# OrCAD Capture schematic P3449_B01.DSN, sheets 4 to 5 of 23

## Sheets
4 0019_40Pin GPIO expansion heade: size Custom
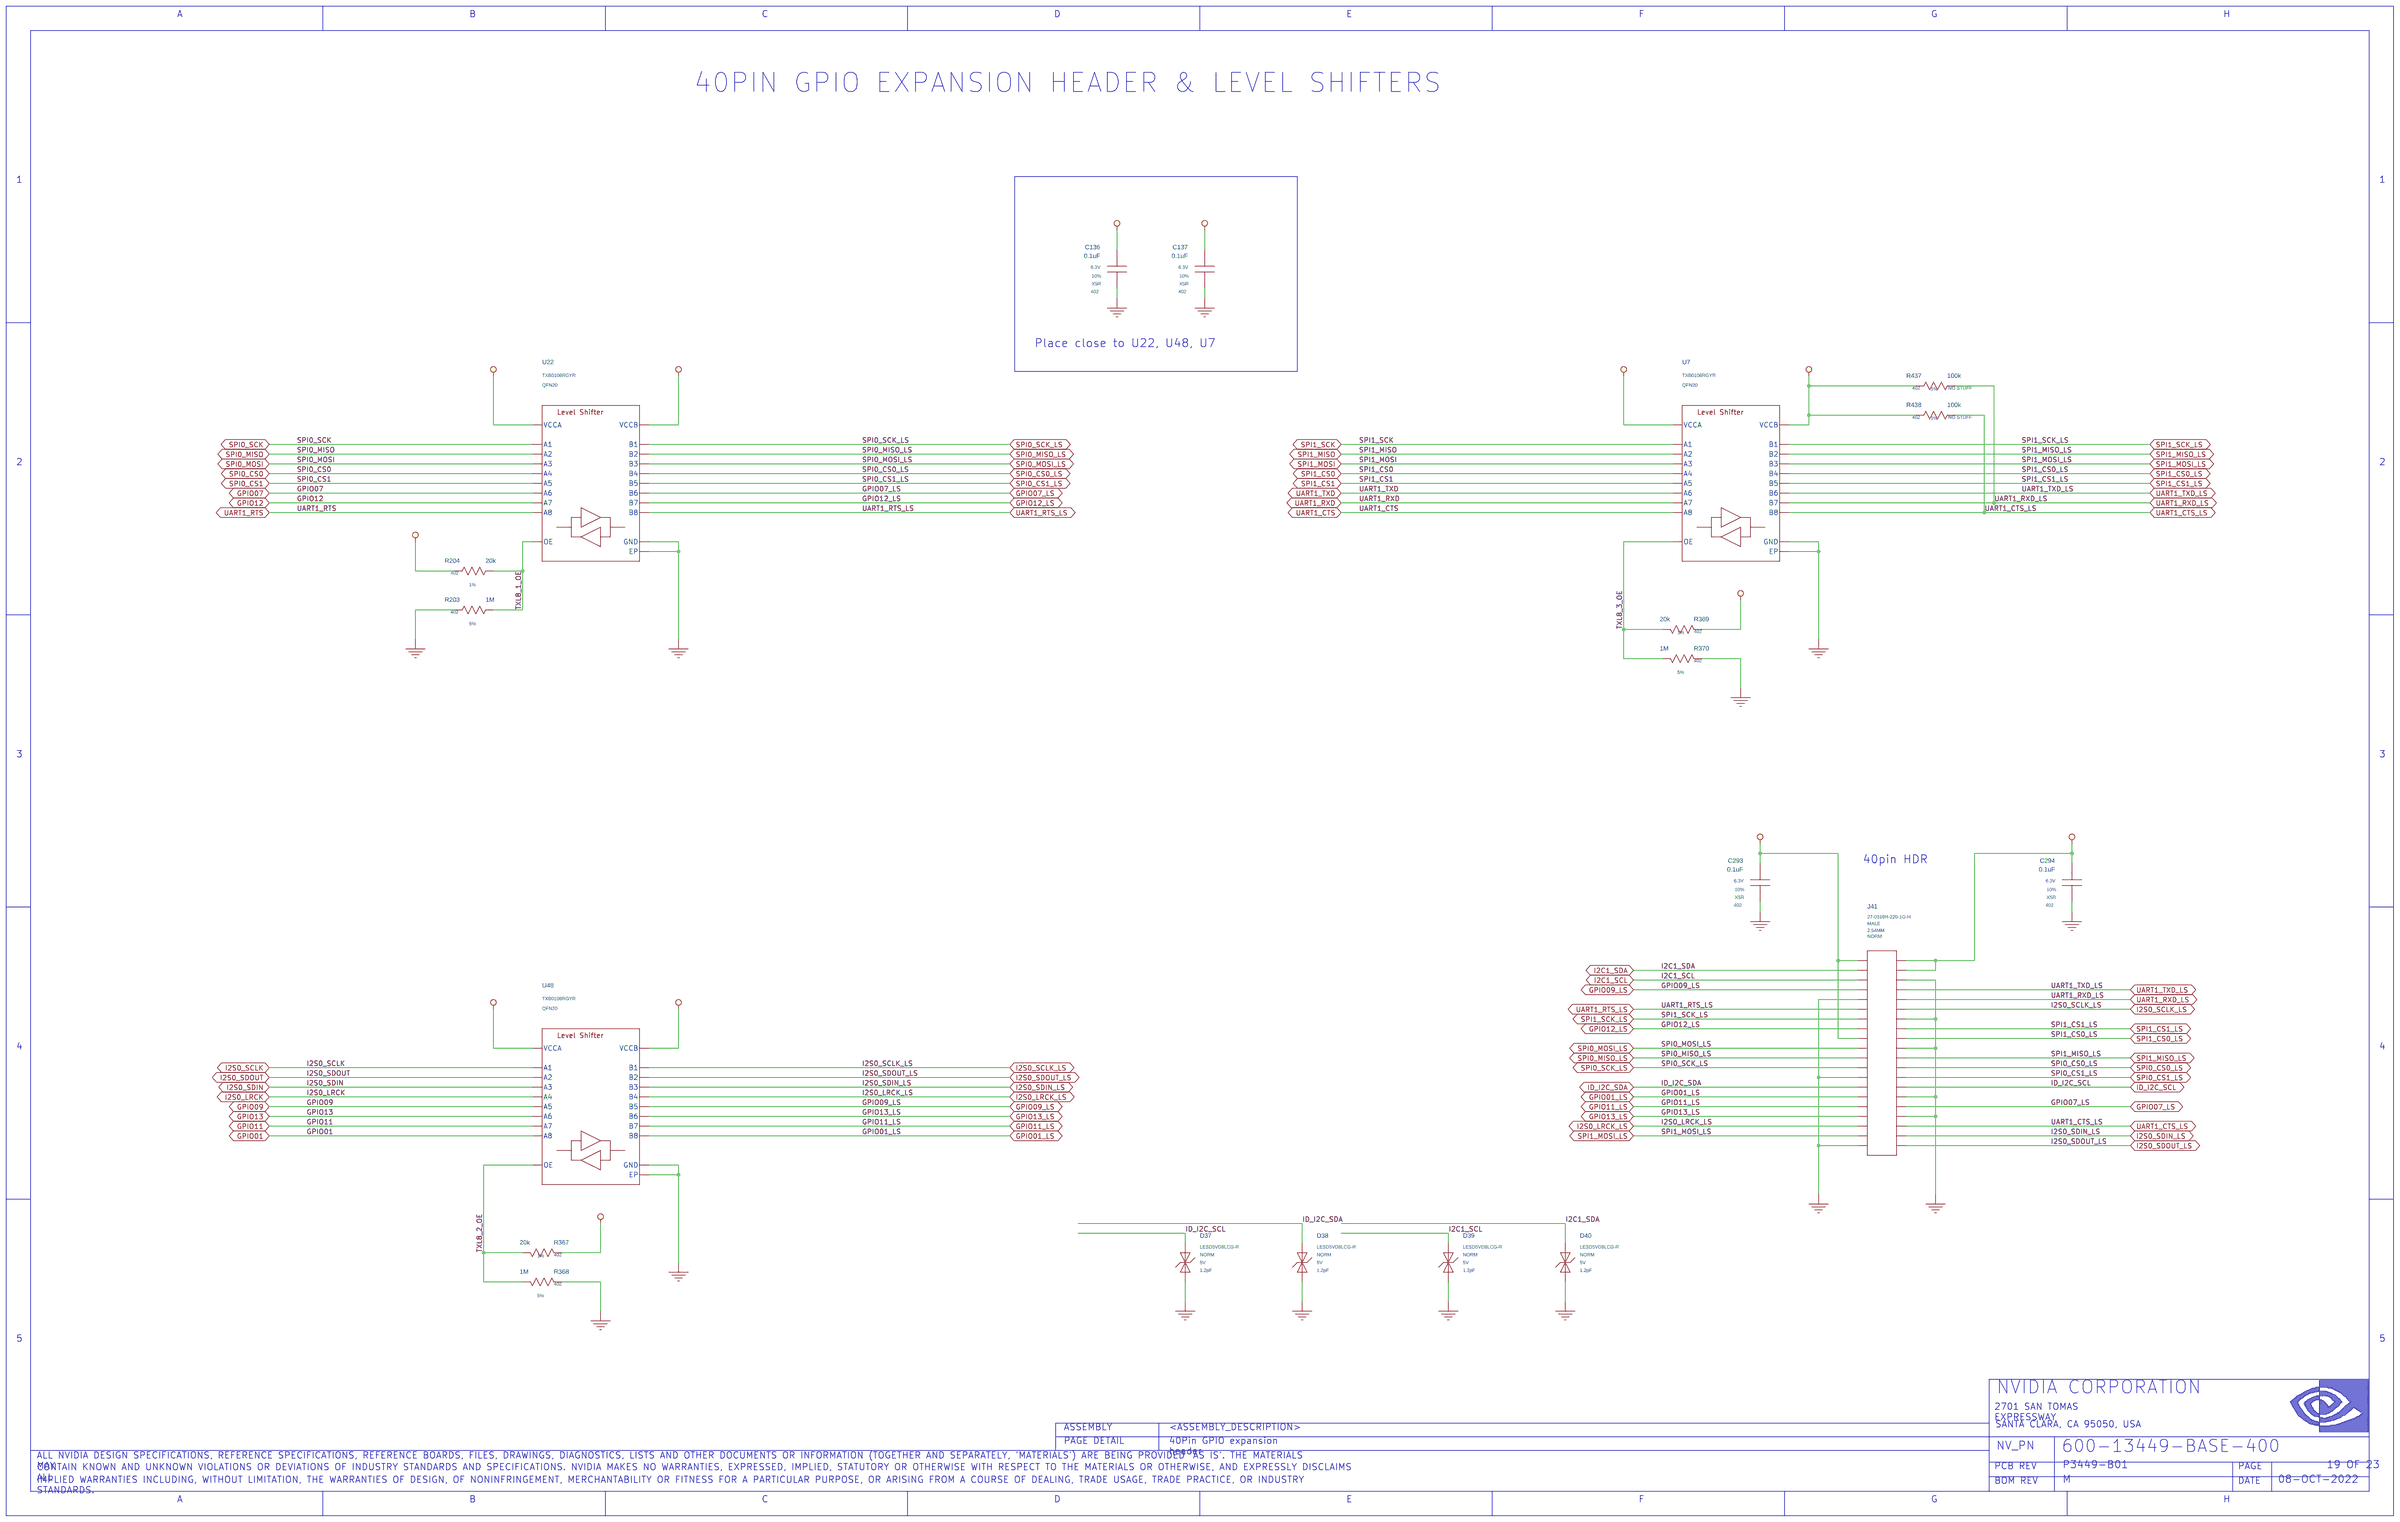
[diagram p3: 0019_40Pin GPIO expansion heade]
5 0018_CAM Connector: size Custom
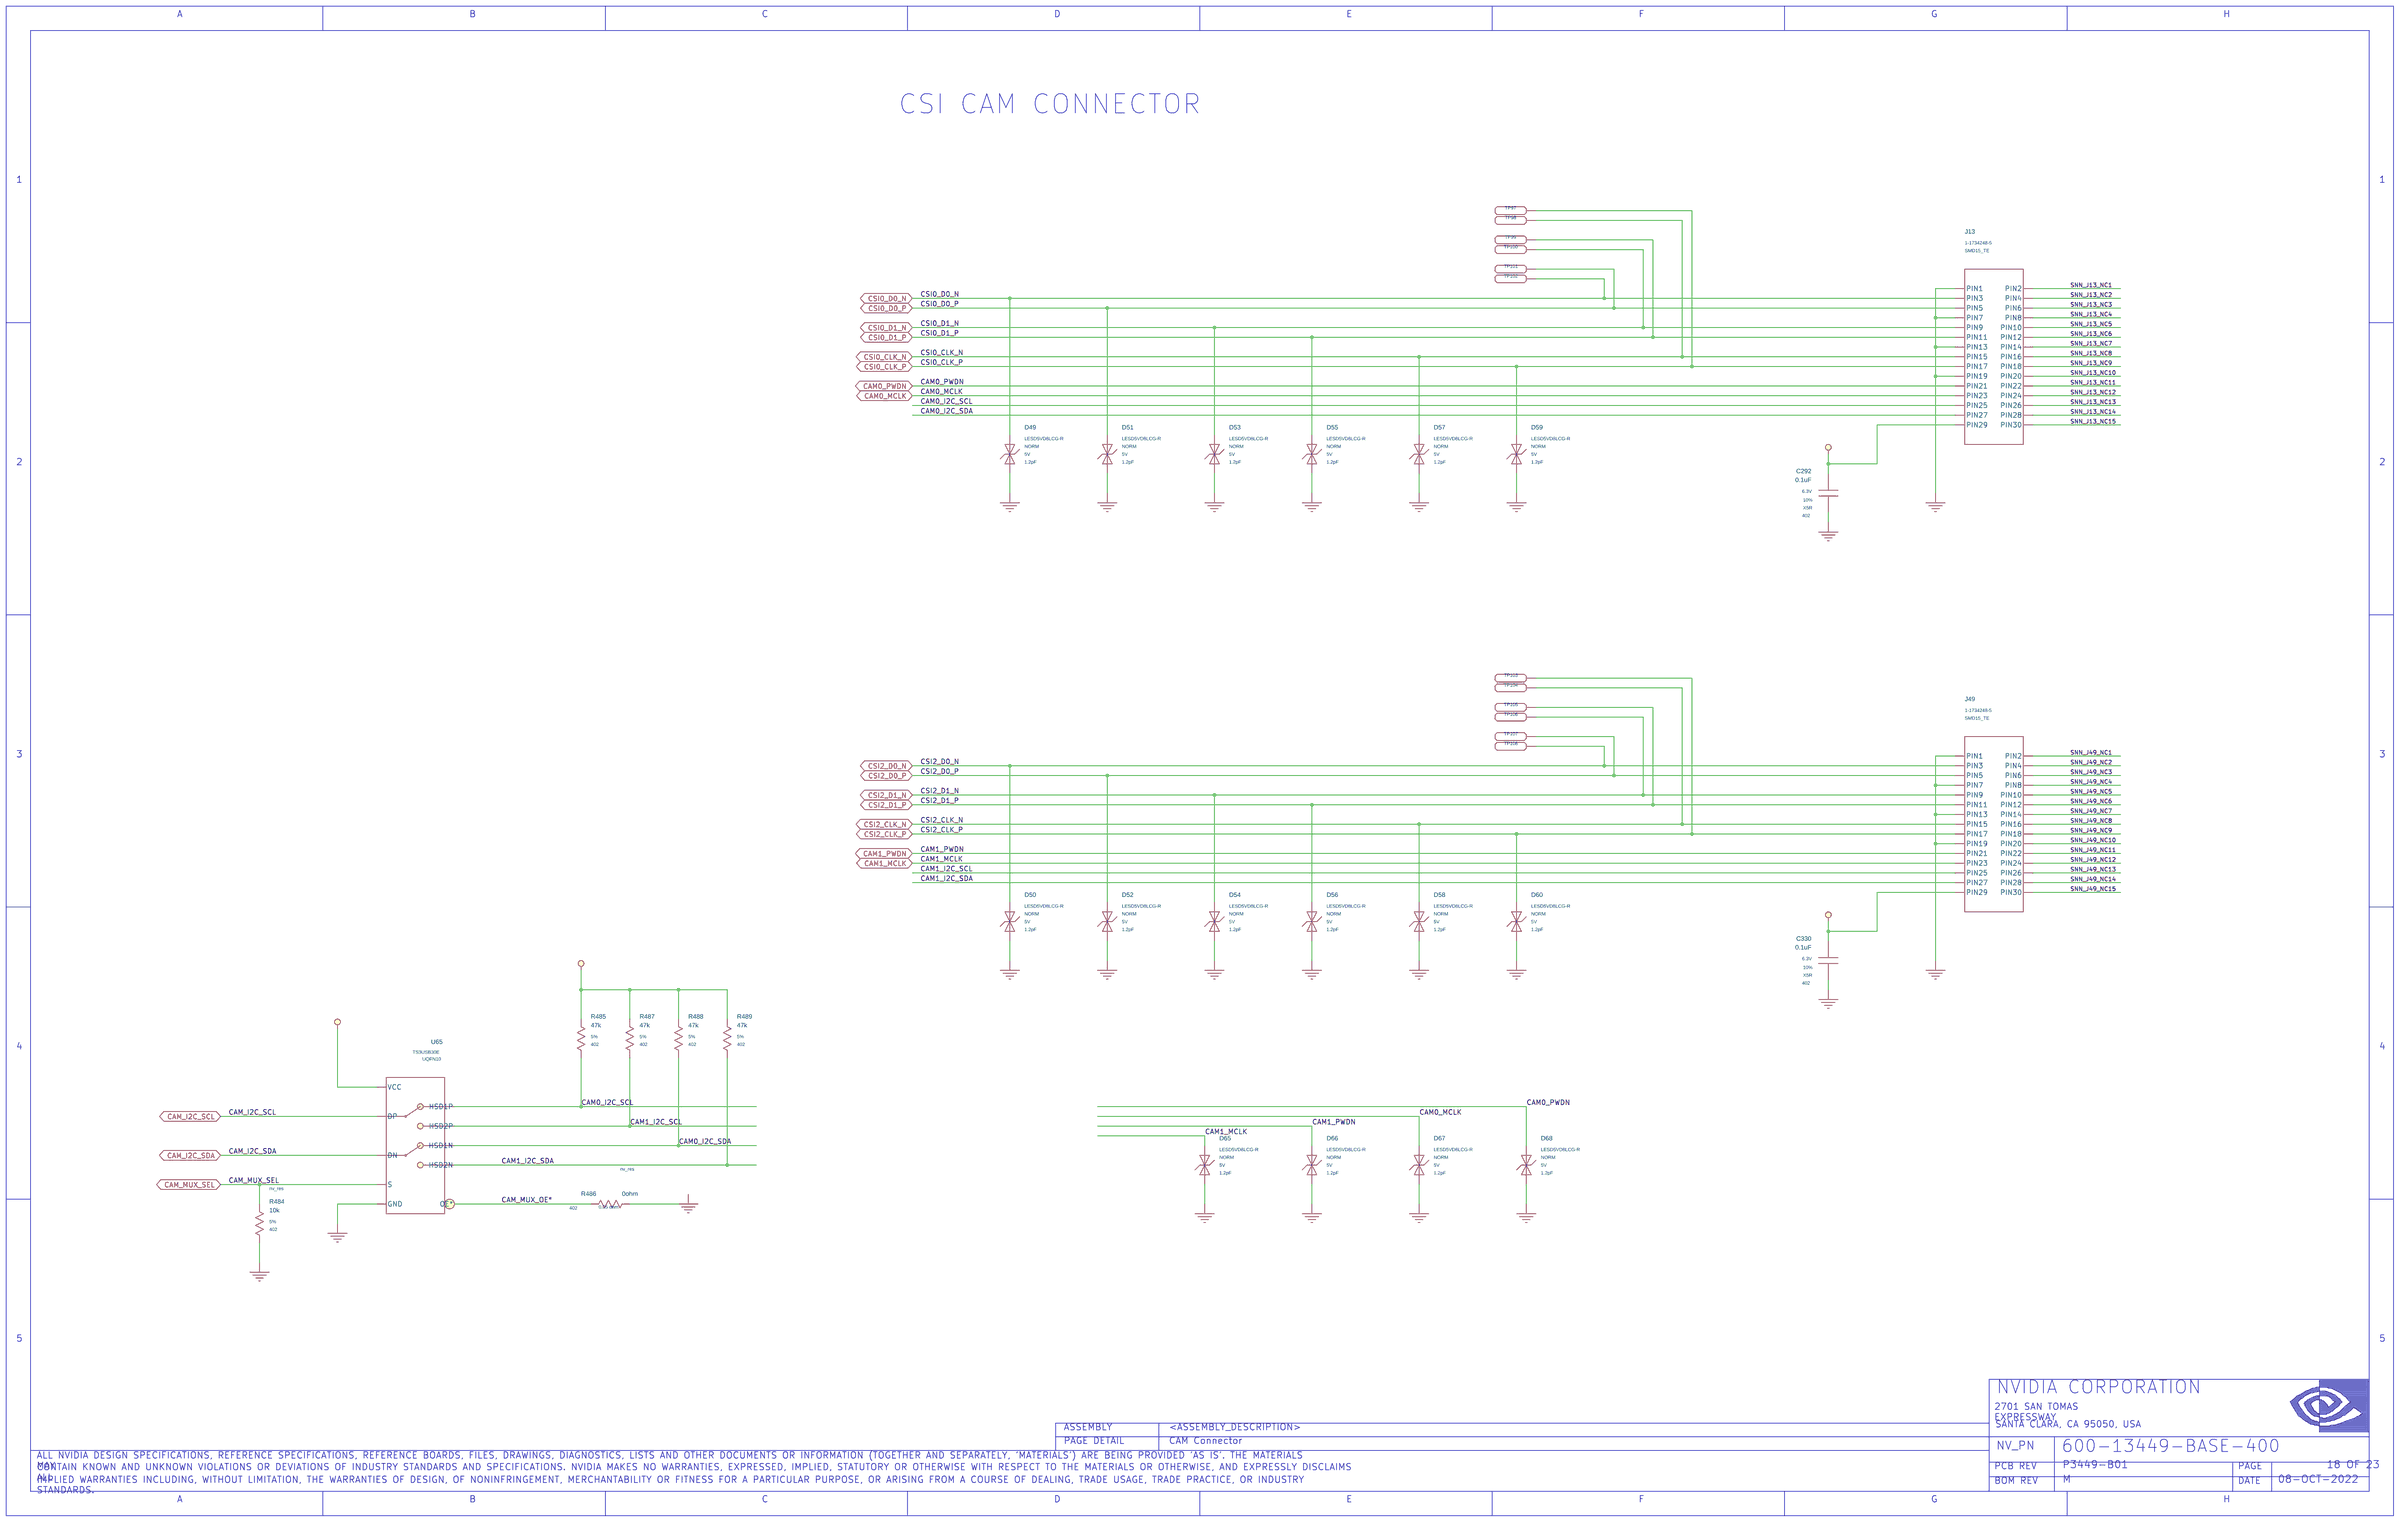
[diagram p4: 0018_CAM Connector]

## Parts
sheet 0018_CAM Connector
C292  0.1uF  [402]
C330  0.1uF  [402]
D49  D_ESD  [DIODE_SMD_010X060]
D50  D_ESD  [DIODE_SMD_010X060]
D51  D_ESD  [DIODE_SMD_010X060]
D52  D_ESD  [DIODE_SMD_010X060]
D53  D_ESD  [DIODE_SMD_010X060]
D54  D_ESD  [DIODE_SMD_010X060]
D55  D_ESD  [DIODE_SMD_010X060]
D56  D_ESD  [DIODE_SMD_010X060]
D57  D_ESD  [DIODE_SMD_010X060]
D58  D_ESD  [DIODE_SMD_010X060]
D59  D_ESD  [DIODE_SMD_010X060]
D60  D_ESD  [DIODE_SMD_010X060]
D65  D_ESD  [DIODE_SMD_010X060]
D66  D_ESD  [DIODE_SMD_010X060]
D67  D_ESD  [DIODE_SMD_010X060]
D68  D_ESD  [DIODE_SMD_010X060]
J13  CON_FPC_15  [CON_FFC_030_SMD_ST_F_P010_ZIF]
J49  CON_FPC_15  [CON_FFC_030_SMD_ST_F_P010_ZIF]
R484  10k  [402]
R485  47k  [402]
R486  0ohm  [402]
R487  47k  [402]
R488  47k  [402]
R489  47k  [402]
TP97  LABTESTPOINT  [LTPB071C125D045C025P]
TP98  LABTESTPOINT  [LTPB071C125D045C025P]
TP99  LABTESTPOINT  [LTPB071C125D045C025P]
TP100  LABTESTPOINT  [LTPB071C125D045C025P]
TP101  LABTESTPOINT  [LTPB071C125D045C025P]
TP102  LABTESTPOINT  [LTPB071C125D045C025P]
TP103  LABTESTPOINT  [LTPB071C125D045C025P]
TP104  LABTESTPOINT  [LTPB071C125D045C025P]
TP105  LABTESTPOINT  [LTPB071C125D045C025P]
TP106  LABTESTPOINT  [LTPB071C125D045C025P]
TP107  LABTESTPOINT  [LTPB071C125D045C025P]
TP108  LABTESTPOINT  [LTPB071C125D045C025P]
U65  U_SW_ANA_USB  [QFN010R_P040_0018X0014]
sheet 0019_40Pin GPIO expansion heade
C136  0.1uF  [402]
C137  0.1uF  [402]
C293  0.1uF  [402]
C294  0.1uF  [402]
D37  D_ESD  [DIODE_SMD_010X060]
D38  D_ESD  [DIODE_SMD_010X060]
D39  D_ESD  [DIODE_SMD_010X060]
D40  D_ESD  [DIODE_SMD_010X060]
J41  HDR_2X20  [CON_HDR_002X020_TH_ST_M_P025_B]
R203  1M  [402]
R204  20k  [402]
R367  20k  [402]
R368  1M  [402]
R369  20k  [402]
R370  1M  [402]
R437  100k  [402]
R438  100k  [402]
U7  U_LEVSHFT_TXB0108  [QFN020R_P050_0045X0035_T031X021_VIAS]
U22  U_LEVSHFT_TXB0108  [QFN020R_P050_0045X0035_T031X021_VIAS]
U48  U_LEVSHFT_TXB0108  [QFN020R_P050_0045X0035_T031X021_VIAS]

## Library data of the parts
C292 = C#1: ASSEMBLY: CAM; CDS_LIB: discrete; CDS_PART_NAME: C_0402-0.1UF,X5R,10%,6.3V,039-0007-000; CDS_PHYS_PART_NAME: C_0402-0.1UF,X5R,10%,6.3V,039-0007-000-0.1UF,039-0007-000; CDS_SEC: 1; CHIPS_PART_NAME: C; DEVICE_TYPENAME: C_0402-01UFX5R1063V039-0007-000-01UF039-0007-000; DRAWING: @P3449_B01_LIB.P3449_B01(SCH_1):PAGE18; ESL: N/A; ESR: N/A; MAT: X5R; MAX_VOLTAGE: 6.3V; NV_PN: 039-0007-000; PATH: I15; PHYS_PAGE: 18; ROT: 2; SEC: 1; SIGNAL_MODEL: nv_cap; TOL: 10%; VER: 1; XY: (-2800,5100)
C330 = C#1: ASSEMBLY: CAM; CDS_LIB: discrete; CDS_PART_NAME: C_0402-0.1UF,X5R,10%,6.3V,039-0007-000; CDS_PHYS_PART_NAME: C_0402-0.1UF,X5R,10%,6.3V,039-0007-000-0.1UF,039-0007-000; CDS_SEC: 1; CHIPS_PART_NAME: C; DEVICE_TYPENAME: C_0402-01UFX5R1063V039-0007-000-01UF039-0007-000; DRAWING: @P3449_B01_LIB.P3449_B01(SCH_1):PAGE18; ESL: N/A; ESR: N/A; MAT: X5R; MAX_VOLTAGE: 6.3V; NV_PN: 039-0007-000; PATH: I27; PHYS_PAGE: 18; ROT: 2; SEC: 1; SIGNAL_MODEL: nv_cap; TOL: 10%; VER: 1; XY: (-2800,2700)
D49 = D_ESD: ASSEMBLY: CAM; BREAKDOWN_VOLTAGE_MIN_TYP: 5.5V; CAPACITANCE_MAX_TYP: 1.2pF; CDS_LIB: discrete; CDS_PART_NAME: D_ESD_NORM-LESD5VD8LCG-R,1 LINE,BI-DIRECTIONAL,5V,0.05UA,5.5V,10V@2A,1.2PF,090-0172-000; CDS_PHYS_PART_NAME: D_ESD_NORM-LESD5VD8LCG-R,1 LINE,BI-DIRECTIONAL,5V,0.05UA,5.5V,10V@2A,1.2PF,090-0172-000-090-0172-000; CDS_SEC: 1; CLAMPING_VOLTAGE: 10V@2A; CONFIGURATION: 1 Line; DEVICE_TYPENAME: D_ESD_NORM-LESD5VD8LCG-R1LINEBI-DIRECTIONAL5V005UA55V10V2A12PF090-0172-000-090-0172-000; DRAWING: @P3449_B01_LIB.P3449_B01(SCH_1):PAGE18; MAX_REVERSE_LEAKAGE_CURRENT: 0.05uA; MAX_REVERSE_VOLTAGE: 5V; NV_NAME: LESD5VD8LCG-R; NV_PN: 090-0172-000; PACK_TYPE: NORM; PATH: I32; PHYS_PAGE: 18; POLARITY: Bi-Directional; ROT: 0; SEC: 1; VER: 2; XY: (-7000,5300)
D50 = D_ESD: ASSEMBLY: CAM; BREAKDOWN_VOLTAGE_MIN_TYP: 5.5V; CAPACITANCE_MAX_TYP: 1.2pF; CDS_LIB: discrete; CDS_PART_NAME: D_ESD_NORM-LESD5VD8LCG-R,1 LINE,BI-DIRECTIONAL,5V,0.05UA,5.5V,10V@2A,1.2PF,090-0172-000; CDS_PHYS_PART_NAME: D_ESD_NORM-LESD5VD8LCG-R,1 LINE,BI-DIRECTIONAL,5V,0.05UA,5.5V,10V@2A,1.2PF,090-0172-000-090-0172-000; CDS_SEC: 1; CLAMPING_VOLTAGE: 10V@2A; CONFIGURATION: 1 Line; DEVICE_TYPENAME: D_ESD_NORM-LESD5VD8LCG-R1LINEBI-DIRECTIONAL5V005UA55V10V2A12PF090-0172-000-090-0172-000; DRAWING: @P3449_B01_LIB.P3449_B01(SCH_1):PAGE18; MAX_REVERSE_LEAKAGE_CURRENT: 0.05uA; MAX_REVERSE_VOLTAGE: 5V; NV_NAME: LESD5VD8LCG-R; NV_PN: 090-0172-000; PACK_TYPE: NORM; PATH: I54; PHYS_PAGE: 18; POLARITY: Bi-Directional; ROT: 0; SEC: 1; VER: 2; XY: (-7000,2900)
D51 = D_ESD: ASSEMBLY: CAM; BREAKDOWN_VOLTAGE_MIN_TYP: 5.5V; CAPACITANCE_MAX_TYP: 1.2pF; CDS_LIB: discrete; CDS_PART_NAME: D_ESD_NORM-LESD5VD8LCG-R,1 LINE,BI-DIRECTIONAL,5V,0.05UA,5.5V,10V@2A,1.2PF,090-0172-000; CDS_PHYS_PART_NAME: D_ESD_NORM-LESD5VD8LCG-R,1 LINE,BI-DIRECTIONAL,5V,0.05UA,5.5V,10V@2A,1.2PF,090-0172-000-090-0172-000; CDS_SEC: 1; CLAMPING_VOLTAGE: 10V@2A; CONFIGURATION: 1 Line; DEVICE_TYPENAME: D_ESD_NORM-LESD5VD8LCG-R1LINEBI-DIRECTIONAL5V005UA55V10V2A12PF090-0172-000-090-0172-000; DRAWING: @P3449_B01_LIB.P3449_B01(SCH_1):PAGE18; MAX_REVERSE_LEAKAGE_CURRENT: 0.05uA; MAX_REVERSE_VOLTAGE: 5V; NV_NAME: LESD5VD8LCG-R; NV_PN: 090-0172-000; PACK_TYPE: NORM; PATH: I33; PHYS_PAGE: 18; POLARITY: Bi-Directional; ROT: 0; SEC: 1; VER: 2; XY: (-6500,5300)
D52 = D_ESD: ASSEMBLY: CAM; BREAKDOWN_VOLTAGE_MIN_TYP: 5.5V; CAPACITANCE_MAX_TYP: 1.2pF; CDS_LIB: discrete; CDS_PART_NAME: D_ESD_NORM-LESD5VD8LCG-R,1 LINE,BI-DIRECTIONAL,5V,0.05UA,5.5V,10V@2A,1.2PF,090-0172-000; CDS_PHYS_PART_NAME: D_ESD_NORM-LESD5VD8LCG-R,1 LINE,BI-DIRECTIONAL,5V,0.05UA,5.5V,10V@2A,1.2PF,090-0172-000-090-0172-000; CDS_SEC: 1; CLAMPING_VOLTAGE: 10V@2A; CONFIGURATION: 1 Line; DEVICE_TYPENAME: D_ESD_NORM-LESD5VD8LCG-R1LINEBI-DIRECTIONAL5V005UA55V10V2A12PF090-0172-000-090-0172-000; DRAWING: @P3449_B01_LIB.P3449_B01(SCH_1):PAGE18; MAX_REVERSE_LEAKAGE_CURRENT: 0.05uA; MAX_REVERSE_VOLTAGE: 5V; NV_NAME: LESD5VD8LCG-R; NV_PN: 090-0172-000; PACK_TYPE: NORM; PATH: I52; PHYS_PAGE: 18; POLARITY: Bi-Directional; ROT: 0; SEC: 1; VER: 2; XY: (-6500,2900)
D53 = D_ESD: ASSEMBLY: CAM; BREAKDOWN_VOLTAGE_MIN_TYP: 5.5V; CAPACITANCE_MAX_TYP: 1.2pF; CDS_LIB: discrete; CDS_PART_NAME: D_ESD_NORM-LESD5VD8LCG-R,1 LINE,BI-DIRECTIONAL,5V,0.05UA,5.5V,10V@2A,1.2PF,090-0172-000; CDS_PHYS_PART_NAME: D_ESD_NORM-LESD5VD8LCG-R,1 LINE,BI-DIRECTIONAL,5V,0.05UA,5.5V,10V@2A,1.2PF,090-0172-000-090-0172-000; CDS_SEC: 1; CLAMPING_VOLTAGE: 10V@2A; CONFIGURATION: 1 Line; DEVICE_TYPENAME: D_ESD_NORM-LESD5VD8LCG-R1LINEBI-DIRECTIONAL5V005UA55V10V2A12PF090-0172-000-090-0172-000; DRAWING: @P3449_B01_LIB.P3449_B01(SCH_1):PAGE18; MAX_REVERSE_LEAKAGE_CURRENT: 0.05uA; MAX_REVERSE_VOLTAGE: 5V; NV_NAME: LESD5VD8LCG-R; NV_PN: 090-0172-000; PACK_TYPE: NORM; PATH: I35; PHYS_PAGE: 18; POLARITY: Bi-Directional; ROT: 0; SEC: 1; VER: 2; XY: (-5950,5300)
D54 = D_ESD: ASSEMBLY: CAM; BREAKDOWN_VOLTAGE_MIN_TYP: 5.5V; CAPACITANCE_MAX_TYP: 1.2pF; CDS_LIB: discrete; CDS_PART_NAME: D_ESD_NORM-LESD5VD8LCG-R,1 LINE,BI-DIRECTIONAL,5V,0.05UA,5.5V,10V@2A,1.2PF,090-0172-000; CDS_PHYS_PART_NAME: D_ESD_NORM-LESD5VD8LCG-R,1 LINE,BI-DIRECTIONAL,5V,0.05UA,5.5V,10V@2A,1.2PF,090-0172-000-090-0172-000; CDS_SEC: 1; CLAMPING_VOLTAGE: 10V@2A; CONFIGURATION: 1 Line; DEVICE_TYPENAME: D_ESD_NORM-LESD5VD8LCG-R1LINEBI-DIRECTIONAL5V005UA55V10V2A12PF090-0172-000-090-0172-000; DRAWING: @P3449_B01_LIB.P3449_B01(SCH_1):PAGE18; MAX_REVERSE_LEAKAGE_CURRENT: 0.05uA; MAX_REVERSE_VOLTAGE: 5V; NV_NAME: LESD5VD8LCG-R; NV_PN: 090-0172-000; PACK_TYPE: NORM; PATH: I51; PHYS_PAGE: 18; POLARITY: Bi-Directional; ROT: 0; SEC: 1; VER: 2; XY: (-5950,2900)
D55 = D_ESD: ASSEMBLY: CAM; BREAKDOWN_VOLTAGE_MIN_TYP: 5.5V; CAPACITANCE_MAX_TYP: 1.2pF; CDS_LIB: discrete; CDS_PART_NAME: D_ESD_NORM-LESD5VD8LCG-R,1 LINE,BI-DIRECTIONAL,5V,0.05UA,5.5V,10V@2A,1.2PF,090-0172-000; CDS_PHYS_PART_NAME: D_ESD_NORM-LESD5VD8LCG-R,1 LINE,BI-DIRECTIONAL,5V,0.05UA,5.5V,10V@2A,1.2PF,090-0172-000-090-0172-000; CDS_SEC: 1; CLAMPING_VOLTAGE: 10V@2A; CONFIGURATION: 1 Line; DEVICE_TYPENAME: D_ESD_NORM-LESD5VD8LCG-R1LINEBI-DIRECTIONAL5V005UA55V10V2A12PF090-0172-000-090-0172-000; DRAWING: @P3449_B01_LIB.P3449_B01(SCH_1):PAGE18; MAX_REVERSE_LEAKAGE_CURRENT: 0.05uA; MAX_REVERSE_VOLTAGE: 5V; NV_NAME: LESD5VD8LCG-R; NV_PN: 090-0172-000; PACK_TYPE: NORM; PATH: I34; PHYS_PAGE: 18; POLARITY: Bi-Directional; ROT: 0; SEC: 1; VER: 2; XY: (-5450,5300)
D56 = D_ESD: ASSEMBLY: CAM; BREAKDOWN_VOLTAGE_MIN_TYP: 5.5V; CAPACITANCE_MAX_TYP: 1.2pF; CDS_LIB: discrete; CDS_PART_NAME: D_ESD_NORM-LESD5VD8LCG-R,1 LINE,BI-DIRECTIONAL,5V,0.05UA,5.5V,10V@2A,1.2PF,090-0172-000; CDS_PHYS_PART_NAME: D_ESD_NORM-LESD5VD8LCG-R,1 LINE,BI-DIRECTIONAL,5V,0.05UA,5.5V,10V@2A,1.2PF,090-0172-000-090-0172-000; CDS_SEC: 1; CLAMPING_VOLTAGE: 10V@2A; CONFIGURATION: 1 Line; DEVICE_TYPENAME: D_ESD_NORM-LESD5VD8LCG-R1LINEBI-DIRECTIONAL5V005UA55V10V2A12PF090-0172-000-090-0172-000; DRAWING: @P3449_B01_LIB.P3449_B01(SCH_1):PAGE18; MAX_REVERSE_LEAKAGE_CURRENT: 0.05uA; MAX_REVERSE_VOLTAGE: 5V; NV_NAME: LESD5VD8LCG-R; NV_PN: 090-0172-000; PACK_TYPE: NORM; PATH: I49; PHYS_PAGE: 18; POLARITY: Bi-Directional; ROT: 0; SEC: 1; VER: 2; XY: (-5450,2900)
D57 = D_ESD: ASSEMBLY: CAM; BREAKDOWN_VOLTAGE_MIN_TYP: 5.5V; CAPACITANCE_MAX_TYP: 1.2pF; CDS_LIB: discrete; CDS_PART_NAME: D_ESD_NORM-LESD5VD8LCG-R,1 LINE,BI-DIRECTIONAL,5V,0.05UA,5.5V,10V@2A,1.2PF,090-0172-000; CDS_PHYS_PART_NAME: D_ESD_NORM-LESD5VD8LCG-R,1 LINE,BI-DIRECTIONAL,5V,0.05UA,5.5V,10V@2A,1.2PF,090-0172-000-090-0172-000; CDS_SEC: 1; CLAMPING_VOLTAGE: 10V@2A; CONFIGURATION: 1 Line; DEVICE_TYPENAME: D_ESD_NORM-LESD5VD8LCG-R1LINEBI-DIRECTIONAL5V005UA55V10V2A12PF090-0172-000-090-0172-000; DRAWING: @P3449_B01_LIB.P3449_B01(SCH_1):PAGE18; MAX_REVERSE_LEAKAGE_CURRENT: 0.05uA; MAX_REVERSE_VOLTAGE: 5V; NV_NAME: LESD5VD8LCG-R; NV_PN: 090-0172-000; PACK_TYPE: NORM; PATH: I37; PHYS_PAGE: 18; POLARITY: Bi-Directional; ROT: 0; SEC: 1; VER: 2; XY: (-4900,5300)
D58 = D_ESD: ASSEMBLY: CAM; BREAKDOWN_VOLTAGE_MIN_TYP: 5.5V; CAPACITANCE_MAX_TYP: 1.2pF; CDS_LIB: discrete; CDS_PART_NAME: D_ESD_NORM-LESD5VD8LCG-R,1 LINE,BI-DIRECTIONAL,5V,0.05UA,5.5V,10V@2A,1.2PF,090-0172-000; CDS_PHYS_PART_NAME: D_ESD_NORM-LESD5VD8LCG-R,1 LINE,BI-DIRECTIONAL,5V,0.05UA,5.5V,10V@2A,1.2PF,090-0172-000-090-0172-000; CDS_SEC: 1; CLAMPING_VOLTAGE: 10V@2A; CONFIGURATION: 1 Line; DEVICE_TYPENAME: D_ESD_NORM-LESD5VD8LCG-R1LINEBI-DIRECTIONAL5V005UA55V10V2A12PF090-0172-000-090-0172-000; DRAWING: @P3449_B01_LIB.P3449_B01(SCH_1):PAGE18; MAX_REVERSE_LEAKAGE_CURRENT: 0.05uA; MAX_REVERSE_VOLTAGE: 5V; NV_NAME: LESD5VD8LCG-R; NV_PN: 090-0172-000; PACK_TYPE: NORM; PATH: I47; PHYS_PAGE: 18; POLARITY: Bi-Directional; ROT: 0; SEC: 1; VER: 2; XY: (-4900,2900)
D59 = D_ESD: ASSEMBLY: CAM; BREAKDOWN_VOLTAGE_MIN_TYP: 5.5V; CAPACITANCE_MAX_TYP: 1.2pF; CDS_LIB: discrete; CDS_PART_NAME: D_ESD_NORM-LESD5VD8LCG-R,1 LINE,BI-DIRECTIONAL,5V,0.05UA,5.5V,10V@2A,1.2PF,090-0172-000; CDS_PHYS_PART_NAME: D_ESD_NORM-LESD5VD8LCG-R,1 LINE,BI-DIRECTIONAL,5V,0.05UA,5.5V,10V@2A,1.2PF,090-0172-000-090-0172-000; CDS_SEC: 1; CLAMPING_VOLTAGE: 10V@2A; CONFIGURATION: 1 Line; DEVICE_TYPENAME: D_ESD_NORM-LESD5VD8LCG-R1LINEBI-DIRECTIONAL5V005UA55V10V2A12PF090-0172-000-090-0172-000; DRAWING: @P3449_B01_LIB.P3449_B01(SCH_1):PAGE18; MAX_REVERSE_LEAKAGE_CURRENT: 0.05uA; MAX_REVERSE_VOLTAGE: 5V; NV_NAME: LESD5VD8LCG-R; NV_PN: 090-0172-000; PACK_TYPE: NORM; PATH: I36; PHYS_PAGE: 18; POLARITY: Bi-Directional; ROT: 0; SEC: 1; VER: 2; XY: (-4400,5300)
D60 = D_ESD: ASSEMBLY: CAM; BREAKDOWN_VOLTAGE_MIN_TYP: 5.5V; CAPACITANCE_MAX_TYP: 1.2pF; CDS_LIB: discrete; CDS_PART_NAME: D_ESD_NORM-LESD5VD8LCG-R,1 LINE,BI-DIRECTIONAL,5V,0.05UA,5.5V,10V@2A,1.2PF,090-0172-000; CDS_PHYS_PART_NAME: D_ESD_NORM-LESD5VD8LCG-R,1 LINE,BI-DIRECTIONAL,5V,0.05UA,5.5V,10V@2A,1.2PF,090-0172-000-090-0172-000; CDS_SEC: 1; CLAMPING_VOLTAGE: 10V@2A; CONFIGURATION: 1 Line; DEVICE_TYPENAME: D_ESD_NORM-LESD5VD8LCG-R1LINEBI-DIRECTIONAL5V005UA55V10V2A12PF090-0172-000-090-0172-000; DRAWING: @P3449_B01_LIB.P3449_B01(SCH_1):PAGE18; MAX_REVERSE_LEAKAGE_CURRENT: 0.05uA; MAX_REVERSE_VOLTAGE: 5V; NV_NAME: LESD5VD8LCG-R; NV_PN: 090-0172-000; PACK_TYPE: NORM; PATH: I45; PHYS_PAGE: 18; POLARITY: Bi-Directional; ROT: 0; SEC: 1; VER: 2; XY: (-4400,2900)
D65 = D_ESD: ASSEMBLY: CAM; BREAKDOWN_VOLTAGE_MIN_TYP: 5.5V; CAPACITANCE_MAX_TYP: 1.2pF; CDS_LIB: discrete; CDS_PART_NAME: D_ESD_NORM-LESD5VD8LCG-R,1 LINE,BI-DIRECTIONAL,5V,0.05UA,5.5V,10V@2A,1.2PF,090-0172-000; CDS_PHYS_PART_NAME: D_ESD_NORM-LESD5VD8LCG-R,1 LINE,BI-DIRECTIONAL,5V,0.05UA,5.5V,10V@2A,1.2PF,090-0172-000-090-0172-000; CDS_SEC: 1; CLAMPING_VOLTAGE: 10V@2A; CONFIGURATION: 1 Line; DEVICE_TYPENAME: D_ESD_NORM-LESD5VD8LCG-R1LINEBI-DIRECTIONAL5V005UA55V10V2A12PF090-0172-000-090-0172-000; DRAWING: @P3449_B01_LIB.P3449_B01(SCH_1):PAGE18; MAX_REVERSE_LEAKAGE_CURRENT: 0.05uA; MAX_REVERSE_VOLTAGE: 5V; NV_NAME: LESD5VD8LCG-R; NV_PN: 090-0172-000; PACK_TYPE: NORM; PATH: I75; PHYS_PAGE: 18; POLARITY: Bi-Directional; ROT: 0; SEC: 1; VER: 2; XY: (-6000,1650)
D66 = D_ESD: ASSEMBLY: CAM; BREAKDOWN_VOLTAGE_MIN_TYP: 5.5V; CAPACITANCE_MAX_TYP: 1.2pF; CDS_LIB: discrete; CDS_PART_NAME: D_ESD_NORM-LESD5VD8LCG-R,1 LINE,BI-DIRECTIONAL,5V,0.05UA,5.5V,10V@2A,1.2PF,090-0172-000; CDS_PHYS_PART_NAME: D_ESD_NORM-LESD5VD8LCG-R,1 LINE,BI-DIRECTIONAL,5V,0.05UA,5.5V,10V@2A,1.2PF,090-0172-000-090-0172-000; CDS_SEC: 1; CLAMPING_VOLTAGE: 10V@2A; CONFIGURATION: 1 Line; DEVICE_TYPENAME: D_ESD_NORM-LESD5VD8LCG-R1LINEBI-DIRECTIONAL5V005UA55V10V2A12PF090-0172-000-090-0172-000; DRAWING: @P3449_B01_LIB.P3449_B01(SCH_1):PAGE18; MAX_REVERSE_LEAKAGE_CURRENT: 0.05uA; MAX_REVERSE_VOLTAGE: 5V; NV_NAME: LESD5VD8LCG-R; NV_PN: 090-0172-000; PACK_TYPE: NORM; PATH: I72; PHYS_PAGE: 18; POLARITY: Bi-Directional; ROT: 0; SEC: 1; VER: 2; XY: (-5450,1650)
D67 = D_ESD: ASSEMBLY: CAM; BREAKDOWN_VOLTAGE_MIN_TYP: 5.5V; CAPACITANCE_MAX_TYP: 1.2pF; CDS_LIB: discrete; CDS_PART_NAME: D_ESD_NORM-LESD5VD8LCG-R,1 LINE,BI-DIRECTIONAL,5V,0.05UA,5.5V,10V@2A,1.2PF,090-0172-000; CDS_PHYS_PART_NAME: D_ESD_NORM-LESD5VD8LCG-R,1 LINE,BI-DIRECTIONAL,5V,0.05UA,5.5V,10V@2A,1.2PF,090-0172-000-090-0172-000; CDS_SEC: 1; CLAMPING_VOLTAGE: 10V@2A; CONFIGURATION: 1 Line; DEVICE_TYPENAME: D_ESD_NORM-LESD5VD8LCG-R1LINEBI-DIRECTIONAL5V005UA55V10V2A12PF090-0172-000-090-0172-000; DRAWING: @P3449_B01_LIB.P3449_B01(SCH_1):PAGE18; MAX_REVERSE_LEAKAGE_CURRENT: 0.05uA; MAX_REVERSE_VOLTAGE: 5V; NV_NAME: LESD5VD8LCG-R; NV_PN: 090-0172-000; PACK_TYPE: NORM; PATH: I73; PHYS_PAGE: 18; POLARITY: Bi-Directional; ROT: 0; SEC: 1; VER: 2; XY: (-4900,1650)
D68 = D_ESD: ASSEMBLY: CAM; BREAKDOWN_VOLTAGE_MIN_TYP: 5.5V; CAPACITANCE_MAX_TYP: 1.2pF; CDS_LIB: discrete; CDS_PART_NAME: D_ESD_NORM-LESD5VD8LCG-R,1 LINE,BI-DIRECTIONAL,5V,0.05UA,5.5V,10V@2A,1.2PF,090-0172-000; CDS_PHYS_PART_NAME: D_ESD_NORM-LESD5VD8LCG-R,1 LINE,BI-DIRECTIONAL,5V,0.05UA,5.5V,10V@2A,1.2PF,090-0172-000-090-0172-000; CDS_SEC: 1; CLAMPING_VOLTAGE: 10V@2A; CONFIGURATION: 1 Line; DEVICE_TYPENAME: D_ESD_NORM-LESD5VD8LCG-R1LINEBI-DIRECTIONAL5V005UA55V10V2A12PF090-0172-000-090-0172-000; DRAWING: @P3449_B01_LIB.P3449_B01(SCH_1):PAGE18; MAX_REVERSE_LEAKAGE_CURRENT: 0.05uA; MAX_REVERSE_VOLTAGE: 5V; NV_NAME: LESD5VD8LCG-R; NV_PN: 090-0172-000; PACK_TYPE: NORM; PATH: I74; PHYS_PAGE: 18; POLARITY: Bi-Directional; ROT: 0; SEC: 1; VER: 2; XY: (-4350,1650)
J13 = CON_FPC_15: ANGLE: 0; ASSEMBLY: CAM; CDS_LIB: electro_mechanic; CDS_PART_NAME: CON_FPC_15_SMD15_TE-1-1734248-5,FEMALE,1MM,0,YES,YES,[ ],NO,NO,N/A,N/A,080-1669-000; CDS_PHYS_PART_NAME: CON_FPC_15_SMD15_TE-1-1734248-5,FEMALE,1MM,0,YES,YES,[ ],NO,NO,N/A,N/A,080-1669-000-080-1669-000; CDS_SEC: 1; DEVICE_TYPENAME: CON_FPC_15_SMD15_TE-1-1734248-5FEMALE1MM0YESYESNONONANA080-1669-000-080-1669-000; DRAWING: @P3449_B01_LIB.P3449_B01(SCH_1):PAGE18; EMI_GROUND_TAB: No; GENDER: Female; LATCHING: [ ]; MAX_CURRENT: N/A; MAX_VOLTAGE: N/A; NV_NAME: 1-1734248-5; NV_PN: 080-1669-000; PACK_TYPE: SMD15_TE; PATH: I14; PHYS_PAGE: 18; PITCH: 1mm; REFLOW: Yes; ROT: 0; SEC: 1; SEC_TYPE: SMD15_TE; SHIELDED: No; SHROUDED: YES; VER: 3; XY: (-1950,5800)
J49 = CON_FPC_15: ANGLE: 0; ASSEMBLY: CAM; CDS_LIB: electro_mechanic; CDS_PART_NAME: CON_FPC_15_SMD15_TE-1-1734248-5,FEMALE,1MM,0,YES,YES,[ ],NO,NO,N/A,N/A,080-1669-000; CDS_PHYS_PART_NAME: CON_FPC_15_SMD15_TE-1-1734248-5,FEMALE,1MM,0,YES,YES,[ ],NO,NO,N/A,N/A,080-1669-000-080-1669-000; CDS_SEC: 1; DEVICE_TYPENAME: CON_FPC_15_SMD15_TE-1-1734248-5FEMALE1MM0YESYESNONONANA080-1669-000-080-1669-000; DRAWING: @P3449_B01_LIB.P3449_B01(SCH_1):PAGE18; EMI_GROUND_TAB: No; GENDER: Female; LATCHING: [ ]; MAX_CURRENT: N/A; MAX_VOLTAGE: N/A; NV_NAME: 1-1734248-5; NV_PN: 080-1669-000; PACK_TYPE: SMD15_TE; PATH: I17; PHYS_PAGE: 18; PITCH: 1mm; REFLOW: Yes; ROT: 0; SEC: 1; SHIELDED: No; SHROUDED: YES; VER: 3; XY: (-1950,3400)
R484 = R: ASSEMBLY: CAM; CDS_LIB: discrete; CDS_PART_NAME: R_0402-10K,5 %,62.5MW,195-0486-000; CDS_PHYS_PART_NAME: R_0402-10K,5 %,62.5MW,195-0486-000-10K,195-0486-000; CDS_SEC: 1; DEVICE_TYPENAME: R_0402-10K5625MW195-0486-000-10K195-0486-000; DRAWING: @P3449_B01_LIB.P3449_B01(SCH_1):PAGE18; MAX_WATTAGE: 62.5mW; NV_PN: 195-0486-000; PATH: I92; PHYS_PAGE: 18; ROT: 0; SEC: 1; SIGNAL_MODEL: nv_res; TOL: 5%; VER: 2; XY: (-10850,1350)
R485 = R: ASSEMBLY: CAM; CDS_LIB: discrete; CDS_PART_NAME: R_0402-47K,5 %,62.5MW,195-0599-000; CDS_PHYS_PART_NAME: R_0402-47K,5 %,62.5MW,195-0599-000-195-0599-000,47K; CDS_SEC: 1; DEVICE_TYPENAME: R_0402-47K5625MW195-0599-000-195-0599-00047K; DRAWING: @P3449_B01_LIB.P3449_B01(SCH_1):PAGE18; MAX_WATTAGE: 62.5mW; NV_PN: 195-0599-000; PATH: I86; PHYS_PAGE: 18; ROT: 0; SEC: 1; SIGNAL_MODEL: nv_res; TOL: 5%; VER: 2; XY: (-9200,2300)
R486 = R#1: ASSEMBLY: CAM; CDS_LIB: discrete; CDS_PART_NAME: R_0402-0OHM,0.05 OHM,62.5MW,195-2655-000; CDS_PHYS_PART_NAME: R_0402-0OHM,0.05 OHM,62.5MW,195-2655-000-0OHM,195-2655-000; CDS_SEC: 1; CHIPS_PART_NAME: R; DEVICE_TYPENAME: R_0402-0OHM005OHM625MW195-2655-000-0OHM195-2655-000; DRAWING: @P3449_B01_LIB.P3449_B01(SCH_1):PAGE18; MAX_WATTAGE: 62.5mW; NV_PN: 195-2655-000; PATH: I94; PHYS_PAGE: 18; ROT: 0; SEC: 1; SIGNAL_MODEL: nv_res; TOL: 0.05 ohm; VER: 1; XY: (-9050,1450)
R487 = R: ASSEMBLY: CAM; CDS_LIB: discrete; CDS_PART_NAME: R_0402-47K,5 %,62.5MW,195-0599-000; CDS_PHYS_PART_NAME: R_0402-47K,5 %,62.5MW,195-0599-000-195-0599-000,47K; CDS_SEC: 1; DEVICE_TYPENAME: R_0402-47K5625MW195-0599-000-195-0599-00047K; DRAWING: @P3449_B01_LIB.P3449_B01(SCH_1):PAGE18; MAX_WATTAGE: 62.5mW; NV_PN: 195-0599-000; PATH: I87; PHYS_PAGE: 18; ROT: 0; SEC: 1; SIGNAL_MODEL: nv_res; TOL: 5%; VER: 2; XY: (-8950,2300)
R488 = R: ASSEMBLY: CAM; CDS_LIB: discrete; CDS_PART_NAME: R_0402-47K,5 %,62.5MW,195-0599-000; CDS_PHYS_PART_NAME: R_0402-47K,5 %,62.5MW,195-0599-000-195-0599-000,47K; CDS_SEC: 1; DEVICE_TYPENAME: R_0402-47K5625MW195-0599-000-195-0599-00047K; DRAWING: @P3449_B01_LIB.P3449_B01(SCH_1):PAGE18; MAX_WATTAGE: 62.5mW; NV_PN: 195-0599-000; PATH: I88; PHYS_PAGE: 18; ROT: 0; SEC: 1; SIGNAL_MODEL: nv_res; TOL: 5%; VER: 2; XY: (-8700,2300)
R489 = R: ASSEMBLY: CAM; CDS_LIB: discrete; CDS_PART_NAME: R_0402-47K,5 %,62.5MW,195-0599-000; CDS_PHYS_PART_NAME: R_0402-47K,5 %,62.5MW,195-0599-000-195-0599-000,47K; CDS_SEC: 1; DEVICE_TYPENAME: R_0402-47K5625MW195-0599-000-195-0599-00047K; DRAWING: @P3449_B01_LIB.P3449_B01(SCH_1):PAGE18; MAX_WATTAGE: 62.5mW; NV_PN: 195-0599-000; PATH: I89; PHYS_PAGE: 18; ROT: 0; SEC: 1; SIGNAL_MODEL: nv_res; TOL: 5%; VER: 2; XY: (-8450,2300)
TP97 = LABTESTPOINT: CDS_LIB: electro_mechanic; CDS_PART_NAME: LABTESTPOINT_PIN-LTPB071C125; CDS_PHYS_PART_NAME: LABTESTPOINT_PIN-LTPB071C125; CDS_SEC: 1; DEVICE_TYPENAME: LABTESTPOINT_PIN-LTPB071C125; DRAWING: @P3449_B01_LIB.P3449_B01(SCH_1):PAGE18; NV_NAME: LTPB071C125; PACK_TYPE: PIN; PATH: I71; PHYS_PAGE: 18; ROT: 0; SEC: 1; VER: 1; XY: (-4350,6550)
TP98 = LABTESTPOINT: CDS_LIB: electro_mechanic; CDS_PART_NAME: LABTESTPOINT_PIN-LTPB071C125; CDS_PHYS_PART_NAME: LABTESTPOINT_PIN-LTPB071C125; CDS_SEC: 1; DEVICE_TYPENAME: LABTESTPOINT_PIN-LTPB071C125; DRAWING: @P3449_B01_LIB.P3449_B01(SCH_1):PAGE18; NV_NAME: LTPB071C125; PACK_TYPE: PIN; PATH: I66; PHYS_PAGE: 18; ROT: 0; SEC: 1; VER: 1; XY: (-4350,6500)
TP99 = LABTESTPOINT: CDS_LIB: electro_mechanic; CDS_PART_NAME: LABTESTPOINT_PIN-LTPB071C125; CDS_PHYS_PART_NAME: LABTESTPOINT_PIN-LTPB071C125; CDS_SEC: 1; DEVICE_TYPENAME: LABTESTPOINT_PIN-LTPB071C125; DRAWING: @P3449_B01_LIB.P3449_B01(SCH_1):PAGE18; NV_NAME: LTPB071C125; PACK_TYPE: PIN; PATH: I67; PHYS_PAGE: 18; ROT: 0; SEC: 1; VER: 1; XY: (-4350,6400)
TP100 = LABTESTPOINT: CDS_LIB: electro_mechanic; CDS_PART_NAME: LABTESTPOINT_PIN-LTPB071C125; CDS_PHYS_PART_NAME: LABTESTPOINT_PIN-LTPB071C125; CDS_SEC: 1; DEVICE_TYPENAME: LABTESTPOINT_PIN-LTPB071C125; DRAWING: @P3449_B01_LIB.P3449_B01(SCH_1):PAGE18; NV_NAME: LTPB071C125; PACK_TYPE: PIN; PATH: I68; PHYS_PAGE: 18; ROT: 0; SEC: 1; VER: 1; XY: (-4350,6350)
TP101 = LABTESTPOINT: CDS_LIB: electro_mechanic; CDS_PART_NAME: LABTESTPOINT_PIN-LTPB071C125; CDS_PHYS_PART_NAME: LABTESTPOINT_PIN-LTPB071C125; CDS_SEC: 1; DEVICE_TYPENAME: LABTESTPOINT_PIN-LTPB071C125; DRAWING: @P3449_B01_LIB.P3449_B01(SCH_1):PAGE18; NV_NAME: LTPB071C125; PACK_TYPE: PIN; PATH: I69; PHYS_PAGE: 18; ROT: 0; SEC: 1; VER: 1; XY: (-4350,6250)
TP102 = LABTESTPOINT: CDS_LIB: electro_mechanic; CDS_PART_NAME: LABTESTPOINT_PIN-LTPB071C125; CDS_PHYS_PART_NAME: LABTESTPOINT_PIN-LTPB071C125; CDS_SEC: 1; DEVICE_TYPENAME: LABTESTPOINT_PIN-LTPB071C125; DRAWING: @P3449_B01_LIB.P3449_B01(SCH_1):PAGE18; NV_NAME: LTPB071C125; PACK_TYPE: PIN; PATH: I70; PHYS_PAGE: 18; ROT: 0; SEC: 1; VER: 1; XY: (-4350,6200)
TP103 = LABTESTPOINT: CDS_LIB: electro_mechanic; CDS_PART_NAME: LABTESTPOINT_PIN-LTPB071C125; CDS_PHYS_PART_NAME: LABTESTPOINT_PIN-LTPB071C125; CDS_SEC: 1; DEVICE_TYPENAME: LABTESTPOINT_PIN-LTPB071C125; DRAWING: @P3449_B01_LIB.P3449_B01(SCH_1):PAGE18; NV_NAME: LTPB071C125; PACK_TYPE: PIN; PATH: I60; PHYS_PAGE: 18; ROT: 0; SEC: 1; VER: 1; XY: (-4350,4150)
TP104 = LABTESTPOINT: CDS_LIB: electro_mechanic; CDS_PART_NAME: LABTESTPOINT_PIN-LTPB071C125; CDS_PHYS_PART_NAME: LABTESTPOINT_PIN-LTPB071C125; CDS_SEC: 1; DEVICE_TYPENAME: LABTESTPOINT_PIN-LTPB071C125; DRAWING: @P3449_B01_LIB.P3449_B01(SCH_1):PAGE18; NV_NAME: LTPB071C125; PACK_TYPE: PIN; PATH: I61; PHYS_PAGE: 18; ROT: 0; SEC: 1; VER: 1; XY: (-4350,4100)
TP105 = LABTESTPOINT: CDS_LIB: electro_mechanic; CDS_PART_NAME: LABTESTPOINT_PIN-LTPB071C125; CDS_PHYS_PART_NAME: LABTESTPOINT_PIN-LTPB071C125; CDS_SEC: 1; DEVICE_TYPENAME: LABTESTPOINT_PIN-LTPB071C125; DRAWING: @P3449_B01_LIB.P3449_B01(SCH_1):PAGE18; NV_NAME: LTPB071C125; PACK_TYPE: PIN; PATH: I62; PHYS_PAGE: 18; ROT: 0; SEC: 1; VER: 1; XY: (-4350,4000)
TP106 = LABTESTPOINT: CDS_LIB: electro_mechanic; CDS_PART_NAME: LABTESTPOINT_PIN-LTPB071C125; CDS_PHYS_PART_NAME: LABTESTPOINT_PIN-LTPB071C125; CDS_SEC: 1; DEVICE_TYPENAME: LABTESTPOINT_PIN-LTPB071C125; DRAWING: @P3449_B01_LIB.P3449_B01(SCH_1):PAGE18; NV_NAME: LTPB071C125; PACK_TYPE: PIN; PATH: I63; PHYS_PAGE: 18; ROT: 0; SEC: 1; VER: 1; XY: (-4350,3950)
TP107 = LABTESTPOINT: CDS_LIB: electro_mechanic; CDS_PART_NAME: LABTESTPOINT_PIN-LTPB071C125; CDS_PHYS_PART_NAME: LABTESTPOINT_PIN-LTPB071C125; CDS_SEC: 1; DEVICE_TYPENAME: LABTESTPOINT_PIN-LTPB071C125; DRAWING: @P3449_B01_LIB.P3449_B01(SCH_1):PAGE18; NV_NAME: LTPB071C125; PACK_TYPE: PIN; PATH: I64; PHYS_PAGE: 18; ROT: 0; SEC: 1; VER: 1; XY: (-4350,3850)
TP108 = LABTESTPOINT: CDS_LIB: electro_mechanic; CDS_PART_NAME: LABTESTPOINT_PIN-LTPB071C125; CDS_PHYS_PART_NAME: LABTESTPOINT_PIN-LTPB071C125; CDS_SEC: 1; DEVICE_TYPENAME: LABTESTPOINT_PIN-LTPB071C125; DRAWING: @P3449_B01_LIB.P3449_B01(SCH_1):PAGE18; NV_NAME: LTPB071C125; PACK_TYPE: PIN; PATH: I65; PHYS_PAGE: 18; ROT: 0; SEC: 1; VER: 1; XY: (-4350,3800)
U65 = U_SW_ANA_USB: ASSEMBLY: CAM; CDS_LIB: analog; CDS_PART_NAME: U_SW_ANA_USB_UQFN10-TS3USB30E,SWITCH - ANALOG,115-0655-000; CDS_PHYS_PART_NAME: U_SW_ANA_USB_UQFN10-TS3USB30E,SWITCH - ANALOG,115-0655-000-115-0655-000; CDS_SEC: 1; DEVICE_TYPENAME: U_SW_ANA_USB_UQFN10-TS3USB30ESWITCH-ANALOG115-0655-000-115-0655-000; DRAWING: @P3449_B01_LIB.P3449_B01(SCH_1):PAGE18; FUNCTION: Switch - Analog; NV_NAME: TS3USB30E; NV_PN: 115-0655-000; PACK_TYPE: UQFN10; PATH: I80; PHYS_PAGE: 18; ROT: 2; SEC: 1; VER: 3; XY: (-10050,1750)
C136 = C#1: ASSEMBLY: GPIO_HDR; CDS_LIB: discrete; CDS_PART_NAME: C_0402-0.1UF,X5R,10%,6.3V,039-0007-000; CDS_PHYS_PART_NAME: C_0402-0.1UF,X5R,10%,6.3V,039-0007-000-0.1UF,039-0007-000; CDS_SEC: 1; CHIPS_PART_NAME: C; DEVICE_TYPENAME: C_0402-01UFX5R1063V039-0007-000-01UF039-0007-000; DRAWING: @P3449_B01_LIB.P3449_B01(SCH_1):PAGE19; ESL: N/A; ESR: N/A; MAT: X5R; MAX_VOLTAGE: 6.3V; NV_PN: 039-0007-000; PATH: I119; PHYS_PAGE: 19; ROT: 2; SEC: 1; SIGNAL_MODEL: nv_cap; TOL: 10%; VER: 1; XY: (-6450,6250)
C137 = C#1: ASSEMBLY: GPIO_HDR; CDS_LIB: discrete; CDS_PART_NAME: C_0402-0.1UF,X5R,10%,6.3V,039-0007-000; CDS_PHYS_PART_NAME: C_0402-0.1UF,X5R,10%,6.3V,039-0007-000-0.1UF,039-0007-000; CDS_SEC: 1; CHIPS_PART_NAME: C; DEVICE_TYPENAME: C_0402-01UFX5R1063V039-0007-000-01UF039-0007-000; DRAWING: @P3449_B01_LIB.P3449_B01(SCH_1):PAGE19; ESL: N/A; ESR: N/A; MAT: X5R; MAX_VOLTAGE: 6.3V; NV_PN: 039-0007-000; PATH: I69; PHYS_PAGE: 19; ROT: 2; SEC: 1; SIGNAL_MODEL: nv_cap; TOL: 10%; VER: 1; XY: (-6000,6250)
C293 = C#1: ASSEMBLY: GPIO_HDR; CDS_LIB: discrete; CDS_PART_NAME: C_0402-0.1UF,X5R,10%,6.3V,039-0007-000; CDS_PHYS_PART_NAME: C_0402-0.1UF,X5R,10%,6.3V,039-0007-000-0.1UF,039-0007-000; CDS_SEC: 1; CHIPS_PART_NAME: C; DEVICE_TYPENAME: C_0402-01UFX5R1063V039-0007-000-01UF039-0007-000; DRAWING: @P3449_B01_LIB.P3449_B01(SCH_1):PAGE19; ESL: N/A; ESR: N/A; MAT: X5R; MAX_VOLTAGE: 6.3V; NV_PN: 039-0007-000; PATH: I267; PHYS_PAGE: 19; ROT: 2; SEC: 1; SIGNAL_MODEL: nv_cap; TOL: 10%; VER: 1; XY: (-3150,3100)
C294 = C#1: ASSEMBLY: GPIO_HDR; CDS_LIB: discrete; CDS_PART_NAME: C_0402-0.1UF,X5R,10%,6.3V,039-0007-000; CDS_PHYS_PART_NAME: C_0402-0.1UF,X5R,10%,6.3V,039-0007-000-0.1UF,039-0007-000; CDS_SEC: 1; CHIPS_PART_NAME: C; DEVICE_TYPENAME: C_0402-01UFX5R1063V039-0007-000-01UF039-0007-000; DRAWING: @P3449_B01_LIB.P3449_B01(SCH_1):PAGE19; ESL: N/A; ESR: N/A; MAT: X5R; MAX_VOLTAGE: 6.3V; NV_PN: 039-0007-000; PATH: I266; PHYS_PAGE: 19; ROT: 2; SEC: 1; SIGNAL_MODEL: nv_cap; TOL: 10%; VER: 1; XY: (-1550,3100)
D37 = D_ESD: ASSEMBLY: GPIO_HDR; BREAKDOWN_VOLTAGE_MIN_TYP: 5.5V; CAPACITANCE_MAX_TYP: 1.2pF; CDS_LIB: discrete; CDS_PART_NAME: D_ESD_NORM-LESD5VD8LCG-R,1 LINE,BI-DIRECTIONAL,5V,0.05UA,5.5V,10V@2A,1.2PF,090-0172-000; CDS_PHYS_PART_NAME: D_ESD_NORM-LESD5VD8LCG-R,1 LINE,BI-DIRECTIONAL,5V,0.05UA,5.5V,10V@2A,1.2PF,090-0172-000-090-0172-000; CDS_SEC: 1; CLAMPING_VOLTAGE: 10V@2A; CONFIGURATION: 1 Line; DEVICE_TYPENAME: D_ESD_NORM-LESD5VD8LCG-R1LINEBI-DIRECTIONAL5V005UA55V10V2A12PF090-0172-000-090-0172-000; DRAWING: @P3449_B01_LIB.P3449_B01(SCH_1):PAGE19; MAX_REVERSE_LEAKAGE_CURRENT: 0.05uA; MAX_REVERSE_VOLTAGE: 5V; NV_NAME: LESD5VD8LCG-R; NV_PN: 090-0172-000; PACK_TYPE: NORM; PATH: I279; PHYS_PAGE: 19; POLARITY: Bi-Directional; ROT: 0; SEC: 1; VER: 2; XY: (-6100,1150)
D38 = D_ESD: ASSEMBLY: GPIO_HDR; BREAKDOWN_VOLTAGE_MIN_TYP: 5.5V; CAPACITANCE_MAX_TYP: 1.2pF; CDS_LIB: discrete; CDS_PART_NAME: D_ESD_NORM-LESD5VD8LCG-R,1 LINE,BI-DIRECTIONAL,5V,0.05UA,5.5V,10V@2A,1.2PF,090-0172-000; CDS_PHYS_PART_NAME: D_ESD_NORM-LESD5VD8LCG-R,1 LINE,BI-DIRECTIONAL,5V,0.05UA,5.5V,10V@2A,1.2PF,090-0172-000-090-0172-000; CDS_SEC: 1; CLAMPING_VOLTAGE: 10V@2A; CONFIGURATION: 1 Line; DEVICE_TYPENAME: D_ESD_NORM-LESD5VD8LCG-R1LINEBI-DIRECTIONAL5V005UA55V10V2A12PF090-0172-000-090-0172-000; DRAWING: @P3449_B01_LIB.P3449_B01(SCH_1):PAGE19; MAX_REVERSE_LEAKAGE_CURRENT: 0.05uA; MAX_REVERSE_VOLTAGE: 5V; NV_NAME: LESD5VD8LCG-R; NV_PN: 090-0172-000; PACK_TYPE: NORM; PATH: I278; PHYS_PAGE: 19; POLARITY: Bi-Directional; ROT: 0; SEC: 1; VER: 2; XY: (-5500,1150)
D39 = D_ESD: ASSEMBLY: GPIO_HDR; BREAKDOWN_VOLTAGE_MIN_TYP: 5.5V; CAPACITANCE_MAX_TYP: 1.2pF; CDS_LIB: discrete; CDS_PART_NAME: D_ESD_NORM-LESD5VD8LCG-R,1 LINE,BI-DIRECTIONAL,5V,0.05UA,5.5V,10V@2A,1.2PF,090-0172-000; CDS_PHYS_PART_NAME: D_ESD_NORM-LESD5VD8LCG-R,1 LINE,BI-DIRECTIONAL,5V,0.05UA,5.5V,10V@2A,1.2PF,090-0172-000-090-0172-000; CDS_SEC: 1; CLAMPING_VOLTAGE: 10V@2A; CONFIGURATION: 1 Line; DEVICE_TYPENAME: D_ESD_NORM-LESD5VD8LCG-R1LINEBI-DIRECTIONAL5V005UA55V10V2A12PF090-0172-000-090-0172-000; DRAWING: @P3449_B01_LIB.P3449_B01(SCH_1):PAGE19; MAX_REVERSE_LEAKAGE_CURRENT: 0.05uA; MAX_REVERSE_VOLTAGE: 5V; NV_NAME: LESD5VD8LCG-R; NV_PN: 090-0172-000; PACK_TYPE: NORM; PATH: I274; PHYS_PAGE: 19; POLARITY: Bi-Directional; ROT: 0; SEC: 1; VER: 2; XY: (-4750,1150)
D40 = D_ESD: ASSEMBLY: GPIO_HDR; BREAKDOWN_VOLTAGE_MIN_TYP: 5.5V; CAPACITANCE_MAX_TYP: 1.2pF; CDS_LIB: discrete; CDS_PART_NAME: D_ESD_NORM-LESD5VD8LCG-R,1 LINE,BI-DIRECTIONAL,5V,0.05UA,5.5V,10V@2A,1.2PF,090-0172-000; CDS_PHYS_PART_NAME: D_ESD_NORM-LESD5VD8LCG-R,1 LINE,BI-DIRECTIONAL,5V,0.05UA,5.5V,10V@2A,1.2PF,090-0172-000-090-0172-000; CDS_SEC: 1; CLAMPING_VOLTAGE: 10V@2A; CONFIGURATION: 1 Line; DEVICE_TYPENAME: D_ESD_NORM-LESD5VD8LCG-R1LINEBI-DIRECTIONAL5V005UA55V10V2A12PF090-0172-000-090-0172-000; DRAWING: @P3449_B01_LIB.P3449_B01(SCH_1):PAGE19; MAX_REVERSE_LEAKAGE_CURRENT: 0.05uA; MAX_REVERSE_VOLTAGE: 5V; NV_NAME: LESD5VD8LCG-R; NV_PN: 090-0172-000; PACK_TYPE: NORM; PATH: I275; PHYS_PAGE: 19; POLARITY: Bi-Directional; ROT: 0; SEC: 1; VER: 2; XY: (-4150,1150)
J41 = HDR_2X20: ANGLE: 0; ASSEMBLY: GPIO_HDR; CDS_LIB: electro_mechanic; CDS_PART_NAME: HDR_2X20_NORM-27-0169H-220-1G-H,MALE,2.54MM,0,YES,NO,NO,1000 V,3 A,074-0221-000; CDS_PHYS_PART_NAME: HDR_2X20_NORM-27-0169H-220-1G-H,MALE,2.54MM,0,YES,NO,NO,1000 V,3 A,074-0221-000-074-0221-000; CDS_SEC: 1; DEVICE_TYPENAME: HDR_2X20_NORM-27-0169H-220-1G-HMALE254MM0YESNONO1000V3A074-0221-000-074-0221-000; DRAWING: @P3449_B01_LIB.P3449_B01(SCH_1):PAGE19; GENDER: MALE; LATCHING: NO; MAX_CURRENT: 3:00 上午; MAX_VOLTAGE: 1000 V; NV_NAME: 27-0169H-220-1G-H; NV_PN: 074-0221-000; PACK_TYPE: NORM; PATH: I68; PHYS_PAGE: 19; PITCH: 2.54MM; REFLOW: YES; ROT: 0; SEC: 1; SEC_TYPE: NORM; SHROUDED: NO; VER: 1; XY: (-2500,2200)
R203 = R#1: ASSEMBLY: GPIO_HDR; CDS_LIB: discrete; CDS_PART_NAME: R_0402-1M,5 %,62.5MW,195-0488-000; CDS_PHYS_PART_NAME: R_0402-1M,5 %,62.5MW,195-0488-000-195-0488-000,1M; CDS_SEC: 1; CHIPS_PART_NAME: R; DEVICE_TYPENAME: R_0402-1M5625MW195-0488-000-195-0488-0001M; DRAWING: @P3449_B01_LIB.P3449_B01(SCH_1):PAGE19; MAX_WATTAGE: 62.5mW; NV_PN: 195-0488-000; PATH: I118; PHYS_PAGE: 19; ROT: 0; SEC: 1; SIGNAL_MODEL: nv_res; TOL: 5%; VER: 1; XY: (-9750,4500)
R204 = R#1: ASSEMBLY: GPIO_HDR; CDS_LIB: discrete; CDS_PART_NAME: R_0402-20K,1 %,62.5MW,195-0150-000; CDS_PHYS_PART_NAME: R_0402-20K,1 %,62.5MW,195-0150-000-195-0150-000,20K; CDS_SEC: 1; CHIPS_PART_NAME: R; DEVICE_TYPENAME: R_0402-20K1625MW195-0150-000-195-0150-00020K; DRAWING: @P3449_B01_LIB.P3449_B01(SCH_1):PAGE19; MAX_WATTAGE: 62.5mW; NV_PN: 195-0150-000; PATH: I117; PHYS_PAGE: 19; ROT: 0; SEC: 1; SIGNAL_MODEL: nv_res; TOL: 1%; VER: 1; XY: (-9750,4700)
R367 = R#1: ASSEMBLY: GPIO_HDR; CDS_LIB: discrete; CDS_PART_NAME: R_0402-20K,1 %,62.5MW,195-0150-000; CDS_PHYS_PART_NAME: R_0402-20K,1 %,62.5MW,195-0150-000-195-0150-000,20K; CDS_SEC: 1; CHIPS_PART_NAME: R; DEVICE_TYPENAME: R_0402-20K1625MW195-0150-000-195-0150-00020K; DRAWING: @P3449_B01_LIB.P3449_B01(SCH_1):PAGE19; MAX_WATTAGE: 62.5mW; NV_PN: 195-0150-000; PATH: I90; PHYS_PAGE: 19; ROT: 2; SEC: 1; SIGNAL_MODEL: nv_res; TOL: 1%; VER: 1; XY: (-9400,1200)
R368 = R#1: ASSEMBLY: GPIO_HDR; CDS_LIB: discrete; CDS_PART_NAME: R_0402-1M,5 %,62.5MW,195-0488-000; CDS_PHYS_PART_NAME: R_0402-1M,5 %,62.5MW,195-0488-000-195-0488-000,1M; CDS_SEC: 1; CHIPS_PART_NAME: R; DEVICE_TYPENAME: R_0402-1M5625MW195-0488-000-195-0488-0001M; DRAWING: @P3449_B01_LIB.P3449_B01(SCH_1):PAGE19; MAX_WATTAGE: 62.5mW; NV_PN: 195-0488-000; PATH: I91; PHYS_PAGE: 19; ROT: 2; SEC: 1; SIGNAL_MODEL: nv_res; TOL: 5%; VER: 1; XY: (-9400,1050)
R369 = R#1: ASSEMBLY: GPIO_HDR; CDS_LIB: discrete; CDS_PART_NAME: R_0402-20K,1 %,62.5MW,195-0150-000; CDS_PHYS_PART_NAME: R_0402-20K,1 %,62.5MW,195-0150-000-195-0150-000,20K; CDS_SEC: 1; CHIPS_PART_NAME: R; DEVICE_TYPENAME: R_0402-20K1625MW195-0150-000-195-0150-00020K; DRAWING: @P3449_B01_LIB.P3449_B01(SCH_1):PAGE19; MAX_WATTAGE: 62.5mW; NV_PN: 195-0150-000; PATH: I150; PHYS_PAGE: 19; ROT: 2; SEC: 1; SIGNAL_MODEL: nv_res; TOL: 1%; VER: 1; XY: (-3550,4400)
R370 = R#1: ASSEMBLY: GPIO_HDR; CDS_LIB: discrete; CDS_PART_NAME: R_0402-1M,5 %,62.5MW,195-0488-000; CDS_PHYS_PART_NAME: R_0402-1M,5 %,62.5MW,195-0488-000-195-0488-000,1M; CDS_SEC: 1; CHIPS_PART_NAME: R; DEVICE_TYPENAME: R_0402-1M5625MW195-0488-000-195-0488-0001M; DRAWING: @P3449_B01_LIB.P3449_B01(SCH_1):PAGE19; MAX_WATTAGE: 62.5mW; NV_PN: 195-0488-000; PATH: I151; PHYS_PAGE: 19; ROT: 2; SEC: 1; SIGNAL_MODEL: nv_res; TOL: 5%; VER: 1; XY: (-3550,4250)
R437 = R#1: ASSEMBLY: GPIO_HDR; CDS_LIB: discrete; CDS_PART_NAME: R_0402-100K,1 %,62.5MW,195-0005-000; CDS_PHYS_PART_NAME: R_0402-100K,1 %,62.5MW,195-0005-000-100K,195-0005-000; CDS_SEC: 1; CHIPS_PART_NAME: R; DEVICE_TYPENAME: R_0402-100K1625MW195-0005-000-100K195-0005-000; DRAWING: @P3449_B01_LIB.P3449_B01(SCH_1):PAGE19; MAX_WATTAGE: 62.5mW; NV_PN: 195-0005-000; PATH: I272; PHYS_PAGE: 19; ROT: 0; SEC: 1; SIGNAL_MODEL: nv_res; SKU: NO STUFF; TOL: 1%; VER: 1; XY: (-2250,5650)
R438 = R#1: ASSEMBLY: GPIO_HDR; CDS_LIB: discrete; CDS_PART_NAME: R_0402-100K,1 %,62.5MW,195-0005-000; CDS_PHYS_PART_NAME: R_0402-100K,1 %,62.5MW,195-0005-000-100K,195-0005-000; CDS_SEC: 1; CHIPS_PART_NAME: R; DEVICE_TYPENAME: R_0402-100K1625MW195-0005-000-100K195-0005-000; DRAWING: @P3449_B01_LIB.P3449_B01(SCH_1):PAGE19; MAX_WATTAGE: 62.5mW; NV_PN: 195-0005-000; PATH: I273; PHYS_PAGE: 19; ROT: 0; SEC: 1; SIGNAL_MODEL: nv_res; SKU: NO STUFF; TOL: 1%; VER: 1; XY: (-2250,5500)
U7 = U_LEVSHFT_TXB0108: ASSEMBLY: GPIO_HDR; CDS_LIB: digital; CDS_PART_NAME: U_LEVSHFT_TXB0108_QFN20-TXB0108RGYR,LEVEL SHIFTER,115-1921-000; CDS_PHYS_PART_NAME: U_LEVSHFT_TXB0108_QFN20-TXB0108RGYR,LEVEL SHIFTER,115-1921-000-115-1921-000; CDS_SEC: 1; DEVICE_TYPENAME: U_LEVSHFT_TXB0108_QFN20-TXB0108RGYRLEVELSHIFTER115-1921-000-115-1921-000; DRAWING: @P3449_B01_LIB.P3449_B01(SCH_1):PAGE19; FUNCTION: Level Shifter; NV_NAME: TXB0108RGYR; NV_PN: 115-1921-000; PACK_TYPE: QFN20; PATH: I140; PHYS_PAGE: 19; ROT: 0; SEC: 1; SEC_TYPE: QFN20; VER: 1; XY: (-3300,5200)
U22 = U_LEVSHFT_TXB0108: ASSEMBLY: GPIO_HDR; CDS_LIB: digital; CDS_PART_NAME: U_LEVSHFT_TXB0108_QFN20-TXB0108RGYR,LEVEL SHIFTER,115-1921-000; CDS_PHYS_PART_NAME: U_LEVSHFT_TXB0108_QFN20-TXB0108RGYR,LEVEL SHIFTER,115-1921-000-115-1921-000; CDS_SEC: 1; DEVICE_TYPENAME: U_LEVSHFT_TXB0108_QFN20-TXB0108RGYRLEVELSHIFTER115-1921-000-115-1921-000; DRAWING: @P3449_B01_LIB.P3449_B01(SCH_1):PAGE19; FUNCTION: Level Shifter; NV_NAME: TXB0108RGYR; NV_PN: 115-1921-000; PACK_TYPE: QFN20; PATH: I116; PHYS_PAGE: 19; ROT: 0; SEC: 1; SEC_TYPE: QFN20; VER: 1; XY: (-9150,5200)
U48 = U_LEVSHFT_TXB0108: ASSEMBLY: GPIO_HDR; CDS_LIB: digital; CDS_PART_NAME: U_LEVSHFT_TXB0108_QFN20-TXB0108RGYR,LEVEL SHIFTER,115-1921-000; CDS_PHYS_PART_NAME: U_LEVSHFT_TXB0108_QFN20-TXB0108RGYR,LEVEL SHIFTER,115-1921-000-115-1921-000; CDS_SEC: 1; DEVICE_TYPENAME: U_LEVSHFT_TXB0108_QFN20-TXB0108RGYRLEVELSHIFTER115-1921-000-115-1921-000; DRAWING: @P3449_B01_LIB.P3449_B01(SCH_1):PAGE19; FUNCTION: Level Shifter; NV_NAME: TXB0108RGYR; NV_PN: 115-1921-000; PACK_TYPE: QFN20; PATH: I89; PHYS_PAGE: 19; ROT: 0; SEC: 1; SEC_TYPE: QFN20; VER: 1; XY: (-9150,2000)

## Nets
GND: C136.2 C137.2 C292.2 C293.2 C294.2 C330.2 D37.2 D38.2 D39.2 D40.2 D49.2 D50.2 D51.2 D52.2 D53.2 D54.2 D55.2 D56.2 D57.2 D58.2 D59.2 D60.2 D65.2 D66.2 D67.2 D68.2 J13.1(PIN1) J13.7(PIN7) J13.13(PIN13) J13.19(PIN19) J41.6 J41.9 J41.14 J41.20 J41.25 J41.30 J41.34 J41.39 J49.1(PIN1) J49.7(PIN7) J49.13(PIN13) J49.19(PIN19) R203.1 R368.1 R370.1 R484.2 R486.2 U7.11(GND) U7.21(EP) U22.11(GND) U22.21(EP) U48.11(GND) U48.21(EP) U65.4(GND) ; also on sheet 1 3 6 7 8 9 10 11 12 13 14 15 16 19
VDD_1V8: C136.1 R204.1 R367.1 R369.1 U7.2(VCCA) U22.2(VCCA) U48.2(VCCA) ; also on sheet 3 6 7 9 11 19
VDD_3V3_SYS: C137.1 C292.1 C293.1 C330.1 J13.29(PIN29) J41.1 J41.17 J49.29(PIN29) R437.1 R438.1 R485.1 R487.1 R488.1 R489.1 U7.19(VCCB) U22.19(VCCB) U48.19(VCCB) U65.9(VCC) ; also on sheet 3 6 7 8 9 11 18 19
VDD_5V_IN: C294.1 J41.2 J41.4 ; also on sheet 3 7 10 11 12 14 15 19
CAM0_I2C_SCL: J13.25(PIN25) R485.2 U65.1(HSD1P)
CAM0_I2C_SDA: J13.27(PIN27) R488.2 U65.7(HSD1N)
CAM0_MCLK: D67.1 J13.23(PIN23) ; also on sheet 18
CAM0_PWDN: D68.1 J13.21(PIN21) ; also on sheet 18
CAM1_I2C_SCL: J49.25(PIN25) R487.2 U65.2(HSD2P)
CAM1_I2C_SDA: J49.27(PIN27) R489.2 U65.6(HSD2N)
CAM1_MCLK: D65.1 J49.23(PIN23) ; also on sheet 18
CAM1_PWDN: D66.1 J49.21(PIN21) ; also on sheet 18
CAM_I2C_SCL: U65.3(DP) ; also on sheet 15 18
CAM_I2C_SDA: U65.5(DN) ; also on sheet 15 18
CAM_MUX_OE*: R486.1 U65.8(OE*)
CAM_MUX_SEL: R484.1 U65.10(S) ; also on sheet 18
CSI0_CLK_N: D57.1 J13.15(PIN15) TP98.1 ; also on sheet 18
CSI0_CLK_P: D59.1 J13.17(PIN17) TP97.1 ; also on sheet 18
CSI0_D0_N: D49.1 J13.3(PIN3) TP102.1 ; also on sheet 18
CSI0_D0_P: D51.1 J13.5(PIN5) TP101.1 ; also on sheet 18
CSI0_D1_N: D53.1 J13.9(PIN9) TP100.1 ; also on sheet 18
CSI0_D1_P: D55.1 J13.11(PIN11) TP99.1 ; also on sheet 18
CSI2_CLK_N: D58.1 J49.15(PIN15) TP104.1 ; also on sheet 18
CSI2_CLK_P: D60.1 J49.17(PIN17) TP103.1 ; also on sheet 18
CSI2_D0_N: D50.1 J49.3(PIN3) TP108.1 ; also on sheet 18
CSI2_D0_P: D52.1 J49.5(PIN5) TP107.1 ; also on sheet 18
CSI2_D1_N: D54.1 J49.9(PIN9) TP106.1 ; also on sheet 18
CSI2_D1_P: D56.1 J49.11(PIN11) TP105.1 ; also on sheet 18
GPIO01: U48.9(A8) ; also on sheet 18
GPIO01_LS: J41.29 U48.12(B8)
GPIO07: U22.7(A6) ; also on sheet 18
GPIO07_LS: J41.32 U22.14(B6)
GPIO09: U48.6(A5) ; also on sheet 18
GPIO09_LS: J41.7 U48.15(B5)
GPIO11: U48.8(A7) ; also on sheet 18
GPIO11_LS: J41.31 U48.13(B7)
GPIO12: U22.8(A7) ; also on sheet 18
GPIO12_LS: J41.15 U22.13(B7)
GPIO13: U48.7(A6) ; also on sheet 18
GPIO13_LS: J41.33 U48.14(B6)
I2C1_SCL: D39.1 J41.5 ; also on sheet 19
I2C1_SDA: D40.1 J41.3 ; also on sheet 19
I2S0_LRCK: U48.5(A4) ; also on sheet 18
I2S0_LRCK_LS: J41.35 U48.16(B4)
I2S0_SCLK: U48.1(A1) ; also on sheet 18
I2S0_SCLK_LS: J41.12 U48.20(B1)
I2S0_SDIN: U48.4(A3) ; also on sheet 18
I2S0_SDIN_LS: J41.38 U48.17(B3)
I2S0_SDOUT: U48.3(A2) ; also on sheet 18
I2S0_SDOUT_LS: J41.40 U48.18(B2)
ID_I2C_SCL: D37.1 J41.28 ; also on sheet 19
ID_I2C_SDA: D38.1 J41.27 ; also on sheet 19
SNN_J13_NC1: J13.2(PIN2)
SNN_J13_NC2: J13.4(PIN4)
SNN_J13_NC3: J13.6(PIN6)
SNN_J13_NC4: J13.8(PIN8)
SNN_J13_NC5: J13.10(PIN10)
SNN_J13_NC6: J13.12(PIN12)
SNN_J13_NC7: J13.14(PIN14)
SNN_J13_NC8: J13.16(PIN16)
SNN_J13_NC9: J13.18(PIN18)
SNN_J13_NC10: J13.20(PIN20)
SNN_J13_NC11: J13.22(PIN22)
SNN_J13_NC12: J13.24(PIN24)
SNN_J13_NC13: J13.26(PIN26)
SNN_J13_NC14: J13.28(PIN28)
SNN_J13_NC15: J13.30(PIN30)
SNN_J49_NC1: J49.2(PIN2)
SNN_J49_NC2: J49.4(PIN4)
SNN_J49_NC3: J49.6(PIN6)
SNN_J49_NC4: J49.8(PIN8)
SNN_J49_NC5: J49.10(PIN10)
SNN_J49_NC6: J49.12(PIN12)
SNN_J49_NC7: J49.14(PIN14)
SNN_J49_NC8: J49.16(PIN16)
SNN_J49_NC9: J49.18(PIN18)
SNN_J49_NC10: J49.20(PIN20)
SNN_J49_NC11: J49.22(PIN22)
SNN_J49_NC12: J49.24(PIN24)
SNN_J49_NC13: J49.26(PIN26)
SNN_J49_NC14: J49.28(PIN28)
SNN_J49_NC15: J49.30(PIN30)
SPI0_CS0: U22.5(A4) ; also on sheet 18
SPI0_CS0_LS: J41.24 U22.16(B4)
SPI0_CS1: U22.6(A5) ; also on sheet 18
SPI0_CS1_LS: J41.26 U22.15(B5)
SPI0_MISO: U22.3(A2) ; also on sheet 18
SPI0_MISO_LS: J41.21 U22.18(B2)
SPI0_MOSI: U22.4(A3) ; also on sheet 18
SPI0_MOSI_LS: J41.19 U22.17(B3)
SPI0_SCK: U22.1(A1) ; also on sheet 18
SPI0_SCK_LS: J41.23 U22.20(B1)
SPI1_CS0: U7.5(A4) ; also on sheet 18
SPI1_CS0_LS: J41.18 U7.16(B4)
SPI1_CS1: U7.6(A5) ; also on sheet 18
SPI1_CS1_LS: J41.16 U7.15(B5)
SPI1_MISO: U7.3(A2) ; also on sheet 18
SPI1_MISO_LS: J41.22 U7.18(B2)
SPI1_MOSI: U7.4(A3) ; also on sheet 18
SPI1_MOSI_LS: J41.37 U7.17(B3)
SPI1_SCK: U7.1(A1) ; also on sheet 18
SPI1_SCK_LS: J41.13 U7.20(B1)
TXL8_1_OE: R203.2 R204.2 U22.10(OE)
TXL8_2_OE: R367.2 R368.2 U48.10(OE)
TXL8_3_OE: R369.2 R370.2 U7.10(OE)
UART1_CTS: U7.9(A8) ; also on sheet 19
UART1_CTS_LS: J41.36 R438.2 U7.12(B8)
UART1_RTS: U22.9(A8) ; also on sheet 19
UART1_RTS_LS: J41.11 U22.12(B8)
UART1_RXD: U7.8(A7) ; also on sheet 19
UART1_RXD_LS: J41.10 R437.2 U7.13(B7)
UART1_TXD: U7.7(A6) ; also on sheet 19
UART1_TXD_LS: J41.8 U7.14(B6)

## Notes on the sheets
sheet 4
- A
- B
- C
- D
- E
- F
- G
- H
- 40PIN GPIO EXPANSION HEADER & LEVEL SHIFTERS
- 1
- 1
- Place close to U22, U48, U7
- 2
- 2
- 3
- 3
- 40pin HDR
- 4
- 4
- 5
- 5
- NVIDIA CORPORATION
- 2701 SAN TOMAS
  EXPRESSWAY
- ASSEMBLY
- <ASSEMBLY_DESCRIPTION>
- SANTA CLARA, CA 95050, USA
- PAGE DETAIL
- 40Pin GPIO expansion
  header
- NV_PN
- 600-13449-BASE-400
- ALL NVIDIA DESIGN SPECIFICATIONS, REFERENCE SPECIFICATIONS, REFERENCE BOARDS, FILES, DRAWINGS, DIAGNOSTICS, LISTS AND OTHER DOCUMENTS OR INFORMATION (TOGETHER AND SEPARATELY, 'MATERIALS') ARE BEING PROVIDED 'AS IS'. THE MATERIALS
  MAY
- CONTAIN KNOWN AND UNKNOWN VIOLATIONS OR DEVIATIONS OF INDUSTRY STANDARDS AND SPECIFICATIONS. NVIDIA MAKES NO WARRANTIES, EXPRESSED, IMPLIED, STATUTORY OR OTHERWISE WITH RESPECT TO THE MATERIALS OR OTHERWISE, AND EXPRESSLY DISCLAIMS
  ALL
- PCB REV
- P3449-B01
- PAGE
- 19 OF 23
- IMPLIED WARRANTIES INCLUDING, WITHOUT LIMITATION, THE WARRANTIES OF DESIGN, OF NONINFRINGEMENT, MERCHANTABILITY OR FITNESS FOR A PARTICULAR PURPOSE, OR ARISING FROM A COURSE OF DEALING, TRADE USAGE, TRADE PRACTICE, OR INDUSTRY
  STANDARDS.
- BOM REV
- M
- DATE
- 08-OCT-2022
- A
- B
- C
- D
- E
- F
- G
- H
sheet 5
- A
- B
- C
- D
- E
- F
- G
- H
- CSI CAM CONNECTOR
- 1
- 1
- 2
- 2
- 3
- 3
- 4
- 4
- 5
- 5
- NVIDIA CORPORATION
- 2701 SAN TOMAS
  EXPRESSWAY
- ASSEMBLY
- <ASSEMBLY_DESCRIPTION>
- SANTA CLARA, CA 95050, USA
- PAGE DETAIL
- CAM Connector
- NV_PN
- 600-13449-BASE-400
- ALL NVIDIA DESIGN SPECIFICATIONS, REFERENCE SPECIFICATIONS, REFERENCE BOARDS, FILES, DRAWINGS, DIAGNOSTICS, LISTS AND OTHER DOCUMENTS OR INFORMATION (TOGETHER AND SEPARATELY, 'MATERIALS') ARE BEING PROVIDED 'AS IS'. THE MATERIALS
  MAY
- CONTAIN KNOWN AND UNKNOWN VIOLATIONS OR DEVIATIONS OF INDUSTRY STANDARDS AND SPECIFICATIONS. NVIDIA MAKES NO WARRANTIES, EXPRESSED, IMPLIED, STATUTORY OR OTHERWISE WITH RESPECT TO THE MATERIALS OR OTHERWISE, AND EXPRESSLY DISCLAIMS
  ALL
- PCB REV
- P3449-B01
- PAGE
- 18 OF 23
- IMPLIED WARRANTIES INCLUDING, WITHOUT LIMITATION, THE WARRANTIES OF DESIGN, OF NONINFRINGEMENT, MERCHANTABILITY OR FITNESS FOR A PARTICULAR PURPOSE, OR ARISING FROM A COURSE OF DEALING, TRADE USAGE, TRADE PRACTICE, OR INDUSTRY
  STANDARDS.
- BOM REV
- M
- DATE
- 08-OCT-2022
- A
- B
- C
- D
- E
- F
- G
- H
